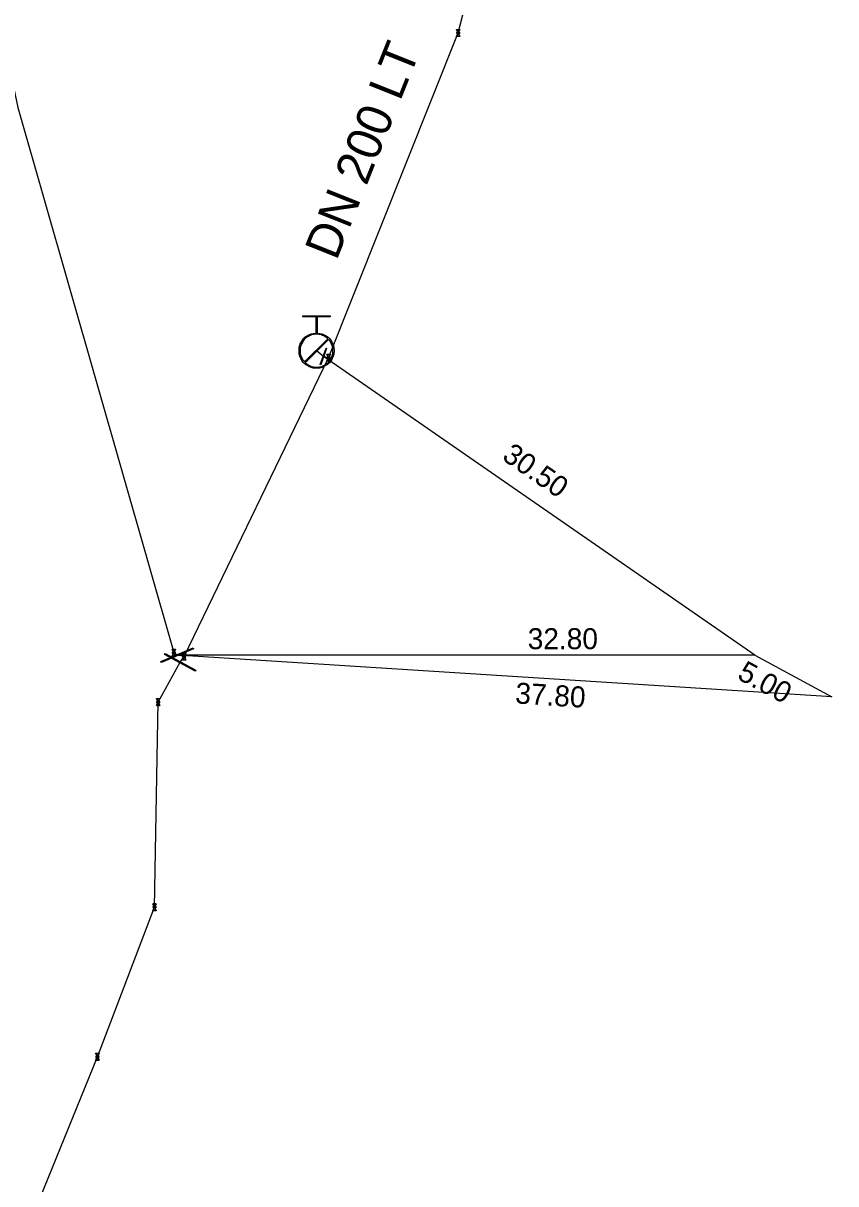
# Model space of a CAD drawing. Extents: x -820257 to -819974, y -1070894 to -1070484.
# Drawn here: x -820183 to -820136.6, y -1070688.1 to -1070621.8 of the extents above; entities that cross this region are included whole.
import ezdxf

# ---------------------------------------------------------------- set-up
doc = ezdxf.new("R2010")
doc.units = 0
for name, color, linetype in [('Hyd-odbočka', 7, 'Continuous'), ('Hyd-šoupě', 7, 'Continuous'), ('Hydrant', 7, 'Continuous'), ('Lomový bod vodovodu', 7, 'Continuous'), ('Oměrka vodovodu', 7, 'Continuous'), ('Oměrka-text', 7, 'Continuous'), ('Roz-řad', 7, 'Continuous'), ('Roz-řad-popis základní', 7, 'Continuous'), ('Řad-šoupě', 7, 'Continuous')]:
    doc.layers.add(name, color=color, linetype=linetype)

msp = doc.modelspace()

# ---------------------------------------------------------------- linework, layer by layer
at = {"layer": 'Hyd-odbočka'}
for p, q in [((-820165.86, -1070640.82), (-820166.25, -1070640.49)), ((-820165.56, -1070640.89), (-820165.86, -1070640.82))]:
    msp.add_line(p, q, dxfattribs=at)
at = {"layer": 'Hyd-šoupě'}
msp.add_lwpolyline([(-820166.041, -1070641.286), (-820165.708, -1070640.343), (-820165.679, -1070640.354), (-820166.012, -1070641.297), (-820166.041, -1070641.286)], dxfattribs=at)
at = {"layer": 'Hydrant'}
for points in [[(-820166.281, -1070639.49), (-820166.281, -1070638.553), (-820167.031, -1070638.553), (-820167.031, -1070638.49), (-820165.469, -1070638.49), (-820165.469, -1070638.553), (-820166.219, -1070638.553), (-820166.219, -1070639.49)], [(-820166.936, -1070641.133), (-820165.607, -1070639.804)], [(-820165.564, -1070639.847), (-820166.893, -1070641.178)]]:
    msp.add_lwpolyline(points, dxfattribs=at)
for points in [[(-820166.219, -1070639.49), (-820165.982, -1070639.498), (-820165.758, -1070639.619), (-820165.52, -1070639.748), (-820165.385, -1070639.988), (-820165.25, -1070640.228), (-820165.25, -1070640.49), (-820165.25, -1070640.75), (-820165.382, -1070640.988), (-820165.514, -1070641.226), (-820165.752, -1070641.358), (-820165.99, -1070641.49), (-820166.25, -1070641.49), (-820166.51, -1070641.49), (-820166.748, -1070641.358), (-820166.986, -1070641.226), (-820167.118, -1070640.988), (-820167.25, -1070640.75), (-820167.25, -1070640.49), (-820167.25, -1070640.228), (-820167.115, -1070639.988), (-820166.98, -1070639.748), (-820166.742, -1070639.619), (-820166.52, -1070639.498), (-820166.281, -1070639.49)], [(-820165.607, -1070639.804), (-820165.689, -1070639.728), (-820165.789, -1070639.674), (-820166.014, -1070639.553), (-820166.25, -1070639.553), (-820166.486, -1070639.553), (-820166.711, -1070639.674), (-820166.936, -1070639.795), (-820167.062, -1070640.019), (-820167.188, -1070640.244), (-820167.188, -1070640.49), (-820167.188, -1070640.734), (-820167.063, -1070640.957), (-820167.01, -1070641.054), (-820166.936, -1070641.133)], [(-820166.893, -1070641.178), (-820166.814, -1070641.25), (-820166.717, -1070641.303), (-820166.494, -1070641.428), (-820166.25, -1070641.428), (-820166.006, -1070641.428), (-820165.782, -1070641.303), (-820165.559, -1070641.179), (-820165.436, -1070640.957), (-820165.313, -1070640.734), (-820165.313, -1070640.49), (-820165.313, -1070640.244), (-820165.439, -1070640.019), (-820165.494, -1070639.924), (-820165.564, -1070639.847)]]:
    msp.add_open_spline(points, degree=3, dxfattribs=at)
at = {"layer": 'Lomový bod vodovodu'}
for points in [[(-820158.188, -1070622.266), (-820158.25, -1070622.13), (-820158.05, -1070622.13), (-820158.113, -1070622.266)], [(-820158.113, -1070622.394), (-820158.05, -1070622.53), (-820158.25, -1070622.53), (-820158.188, -1070622.394)], [(-820158.128, -1070622.259), (-820158.074, -1070622.143), (-820158.228, -1070622.143), (-820158.173, -1070622.259)], [(-820158.173, -1070622.401), (-820158.228, -1070622.518), (-820158.074, -1070622.518), (-820158.128, -1070622.401)], [(-820158.182, -1070622.383), (-820158.158, -1070622.33), (-820158.182, -1070622.277)], [(-820158.168, -1070622.27), (-820158.15, -1070622.308), (-820158.133, -1070622.27)], [(-820158.133, -1070622.39), (-820158.15, -1070622.352), (-820158.168, -1070622.39)], [(-820158.118, -1070622.277), (-820158.142, -1070622.33), (-820158.118, -1070622.383)], [(-820165.598, -1070640.826), (-820165.66, -1070640.69), (-820165.46, -1070640.69), (-820165.523, -1070640.826)], [(-820165.523, -1070640.954), (-820165.46, -1070641.09), (-820165.66, -1070641.09), (-820165.598, -1070640.954)], [(-820165.538, -1070640.819), (-820165.484, -1070640.703), (-820165.638, -1070640.703), (-820165.583, -1070640.819)], [(-820165.583, -1070640.961), (-820165.638, -1070641.078), (-820165.484, -1070641.078), (-820165.538, -1070640.961)], [(-820165.592, -1070640.943), (-820165.568, -1070640.89), (-820165.592, -1070640.837)], [(-820165.578, -1070640.83), (-820165.56, -1070640.868), (-820165.543, -1070640.83)], [(-820165.543, -1070640.95), (-820165.56, -1070640.912), (-820165.578, -1070640.95)], [(-820165.528, -1070640.837), (-820165.552, -1070640.89), (-820165.528, -1070640.943)], [(-820174.448, -1070657.686), (-820174.51, -1070657.55), (-820174.31, -1070657.55), (-820174.373, -1070657.686)], [(-820174.388, -1070657.679), (-820174.334, -1070657.563), (-820174.488, -1070657.563), (-820174.433, -1070657.679)], [(-820174.373, -1070657.814), (-820174.31, -1070657.95), (-820174.51, -1070657.95), (-820174.448, -1070657.814)], [(-820174.433, -1070657.821), (-820174.488, -1070657.938), (-820174.334, -1070657.938), (-820174.388, -1070657.821)], [(-820174.442, -1070657.803), (-820174.418, -1070657.75), (-820174.442, -1070657.697)], [(-820174.428, -1070657.69), (-820174.41, -1070657.728), (-820174.393, -1070657.69)], [(-820174.393, -1070657.81), (-820174.41, -1070657.772), (-820174.428, -1070657.81)], [(-820174.378, -1070657.697), (-820174.402, -1070657.75), (-820174.378, -1070657.803)], [(-820173.858, -1070657.906), (-820173.92, -1070657.77), (-820173.72, -1070657.77), (-820173.783, -1070657.906)], [(-820173.783, -1070658.034), (-820173.72, -1070658.17), (-820173.92, -1070658.17), (-820173.858, -1070658.034)], [(-820173.798, -1070657.899), (-820173.744, -1070657.783), (-820173.898, -1070657.783), (-820173.843, -1070657.899)], [(-820173.843, -1070658.041), (-820173.898, -1070658.158), (-820173.744, -1070658.158), (-820173.798, -1070658.041)], [(-820173.852, -1070658.023), (-820173.828, -1070657.97), (-820173.852, -1070657.917)], [(-820173.838, -1070657.91), (-820173.82, -1070657.948), (-820173.803, -1070657.91)], [(-820173.803, -1070658.03), (-820173.82, -1070657.992), (-820173.838, -1070658.03)], [(-820173.788, -1070657.917), (-820173.812, -1070657.97), (-820173.788, -1070658.023)], [(-820175.338, -1070660.516), (-820175.4, -1070660.38), (-820175.2, -1070660.38), (-820175.263, -1070660.516)], [(-820175.263, -1070660.644), (-820175.2, -1070660.78), (-820175.4, -1070660.78), (-820175.338, -1070660.644)], [(-820175.278, -1070660.509), (-820175.224, -1070660.393), (-820175.378, -1070660.393), (-820175.323, -1070660.509)], [(-820175.323, -1070660.651), (-820175.378, -1070660.768), (-820175.224, -1070660.768), (-820175.278, -1070660.651)], [(-820175.332, -1070660.633), (-820175.308, -1070660.58), (-820175.332, -1070660.527)], [(-820175.318, -1070660.52), (-820175.3, -1070660.558), (-820175.283, -1070660.52)], [(-820175.283, -1070660.64), (-820175.3, -1070660.602), (-820175.318, -1070660.64)], [(-820175.268, -1070660.527), (-820175.292, -1070660.58), (-820175.268, -1070660.633)], [(-820175.548, -1070672.236), (-820175.61, -1070672.1), (-820175.41, -1070672.1), (-820175.473, -1070672.236)], [(-820175.488, -1070672.229), (-820175.434, -1070672.113), (-820175.588, -1070672.113), (-820175.533, -1070672.229)], [(-820175.542, -1070672.353), (-820175.518, -1070672.3), (-820175.542, -1070672.247)], [(-820175.528, -1070672.24), (-820175.51, -1070672.278), (-820175.493, -1070672.24)], [(-820175.478, -1070672.247), (-820175.502, -1070672.3), (-820175.478, -1070672.353)], [(-820175.473, -1070672.364), (-820175.41, -1070672.5), (-820175.61, -1070672.5), (-820175.548, -1070672.364)], [(-820175.533, -1070672.371), (-820175.588, -1070672.488), (-820175.434, -1070672.488), (-820175.488, -1070672.371)], [(-820175.493, -1070672.36), (-820175.51, -1070672.322), (-820175.528, -1070672.36)], [(-820178.818, -1070680.786), (-820178.88, -1070680.65), (-820178.68, -1070680.65), (-820178.743, -1070680.786)], [(-820178.758, -1070680.779), (-820178.704, -1070680.663), (-820178.858, -1070680.663), (-820178.803, -1070680.779)], [(-820178.812, -1070680.903), (-820178.788, -1070680.85), (-820178.812, -1070680.797)], [(-820178.798, -1070680.79), (-820178.78, -1070680.828), (-820178.763, -1070680.79)], [(-820178.763, -1070680.91), (-820178.78, -1070680.872), (-820178.798, -1070680.91)], [(-820178.748, -1070680.797), (-820178.772, -1070680.85), (-820178.748, -1070680.903)], [(-820178.743, -1070680.914), (-820178.68, -1070681.05), (-820178.88, -1070681.05), (-820178.818, -1070680.914)], [(-820178.803, -1070680.921), (-820178.858, -1070681.038), (-820178.704, -1070681.038), (-820178.758, -1070680.921)]]:
    msp.add_lwpolyline(points, dxfattribs=at)
for points in [[(-820158.188, -1070622.394), (-820158.205, -1070622.385), (-820158.215, -1070622.367), (-820158.225, -1070622.35), (-820158.225, -1070622.33), (-820158.225, -1070622.31), (-820158.215, -1070622.293), (-820158.205, -1070622.275), (-820158.188, -1070622.266)], [(-820158.182, -1070622.277), (-820158.196, -1070622.285), (-820158.204, -1070622.299), (-820158.212, -1070622.314), (-820158.212, -1070622.33), (-820158.212, -1070622.346), (-820158.204, -1070622.361), (-820158.196, -1070622.375), (-820158.182, -1070622.383)], [(-820158.173, -1070622.259), (-820158.162, -1070622.255), (-820158.15, -1070622.255), (-820158.139, -1070622.255), (-820158.128, -1070622.259)], [(-820158.128, -1070622.401), (-820158.138, -1070622.405), (-820158.15, -1070622.405), (-820158.162, -1070622.405), (-820158.173, -1070622.401)], [(-820158.133, -1070622.27), (-820158.141, -1070622.268), (-820158.15, -1070622.268), (-820158.159, -1070622.268), (-820158.168, -1070622.27)], [(-820158.168, -1070622.39), (-820158.159, -1070622.392), (-820158.15, -1070622.392), (-820158.141, -1070622.392), (-820158.133, -1070622.39)], [(-820158.118, -1070622.383), (-820158.104, -1070622.375), (-820158.096, -1070622.361), (-820158.088, -1070622.346), (-820158.088, -1070622.33), (-820158.088, -1070622.314), (-820158.096, -1070622.299), (-820158.104, -1070622.285), (-820158.118, -1070622.277)], [(-820158.113, -1070622.266), (-820158.095, -1070622.275), (-820158.085, -1070622.293), (-820158.075, -1070622.31), (-820158.075, -1070622.33), (-820158.075, -1070622.35), (-820158.085, -1070622.367), (-820158.095, -1070622.385), (-820158.113, -1070622.394)], [(-820165.598, -1070640.954), (-820165.615, -1070640.945), (-820165.625, -1070640.927), (-820165.635, -1070640.91), (-820165.635, -1070640.89), (-820165.635, -1070640.87), (-820165.625, -1070640.853), (-820165.615, -1070640.835), (-820165.598, -1070640.826)], [(-820165.592, -1070640.837), (-820165.606, -1070640.845), (-820165.614, -1070640.859), (-820165.622, -1070640.874), (-820165.622, -1070640.89), (-820165.622, -1070640.906), (-820165.614, -1070640.921), (-820165.606, -1070640.935), (-820165.592, -1070640.943)], [(-820165.583, -1070640.819), (-820165.572, -1070640.815), (-820165.56, -1070640.815), (-820165.549, -1070640.815), (-820165.538, -1070640.819)], [(-820165.538, -1070640.961), (-820165.548, -1070640.965), (-820165.56, -1070640.965), (-820165.572, -1070640.965), (-820165.583, -1070640.961)], [(-820165.543, -1070640.83), (-820165.551, -1070640.828), (-820165.56, -1070640.828), (-820165.569, -1070640.828), (-820165.578, -1070640.83)], [(-820165.578, -1070640.95), (-820165.569, -1070640.952), (-820165.56, -1070640.952), (-820165.551, -1070640.952), (-820165.543, -1070640.95)], [(-820165.528, -1070640.943), (-820165.514, -1070640.935), (-820165.506, -1070640.921), (-820165.498, -1070640.906), (-820165.498, -1070640.89), (-820165.498, -1070640.874), (-820165.506, -1070640.859), (-820165.514, -1070640.845), (-820165.528, -1070640.837)], [(-820165.523, -1070640.826), (-820165.505, -1070640.835), (-820165.495, -1070640.853), (-820165.485, -1070640.87), (-820165.485, -1070640.89), (-820165.485, -1070640.91), (-820165.495, -1070640.927), (-820165.505, -1070640.945), (-820165.523, -1070640.954)], [(-820174.448, -1070657.814), (-820174.465, -1070657.805), (-820174.475, -1070657.787), (-820174.485, -1070657.77), (-820174.485, -1070657.75), (-820174.485, -1070657.73), (-820174.475, -1070657.713), (-820174.465, -1070657.695), (-820174.448, -1070657.686)], [(-820174.442, -1070657.697), (-820174.456, -1070657.705), (-820174.464, -1070657.719), (-820174.472, -1070657.734), (-820174.472, -1070657.75), (-820174.472, -1070657.766), (-820174.464, -1070657.781), (-820174.456, -1070657.795), (-820174.442, -1070657.803)], [(-820174.433, -1070657.679), (-820174.422, -1070657.675), (-820174.41, -1070657.675), (-820174.399, -1070657.675), (-820174.388, -1070657.679)], [(-820174.388, -1070657.821), (-820174.398, -1070657.825), (-820174.41, -1070657.825), (-820174.422, -1070657.825), (-820174.433, -1070657.821)], [(-820174.393, -1070657.69), (-820174.401, -1070657.688), (-820174.41, -1070657.688), (-820174.419, -1070657.688), (-820174.428, -1070657.69)], [(-820174.428, -1070657.81), (-820174.419, -1070657.812), (-820174.41, -1070657.812), (-820174.401, -1070657.812), (-820174.393, -1070657.81)], [(-820174.378, -1070657.803), (-820174.364, -1070657.795), (-820174.356, -1070657.781), (-820174.348, -1070657.766), (-820174.348, -1070657.75), (-820174.348, -1070657.734), (-820174.356, -1070657.719), (-820174.364, -1070657.705), (-820174.378, -1070657.697)], [(-820174.373, -1070657.686), (-820174.355, -1070657.695), (-820174.345, -1070657.713), (-820174.335, -1070657.73), (-820174.335, -1070657.75), (-820174.335, -1070657.77), (-820174.345, -1070657.787), (-820174.355, -1070657.805), (-820174.373, -1070657.814)], [(-820173.858, -1070658.034), (-820173.875, -1070658.025), (-820173.885, -1070658.007), (-820173.895, -1070657.99), (-820173.895, -1070657.97), (-820173.895, -1070657.95), (-820173.885, -1070657.933), (-820173.875, -1070657.915), (-820173.858, -1070657.906)], [(-820173.852, -1070657.917), (-820173.866, -1070657.925), (-820173.874, -1070657.939), (-820173.882, -1070657.954), (-820173.882, -1070657.97), (-820173.882, -1070657.986), (-820173.874, -1070658.001), (-820173.866, -1070658.015), (-820173.852, -1070658.023)], [(-820173.843, -1070657.899), (-820173.832, -1070657.895), (-820173.82, -1070657.895), (-820173.809, -1070657.895), (-820173.798, -1070657.899)], [(-820173.798, -1070658.041), (-820173.808, -1070658.045), (-820173.82, -1070658.045), (-820173.832, -1070658.045), (-820173.843, -1070658.041)], [(-820173.803, -1070657.91), (-820173.811, -1070657.908), (-820173.82, -1070657.908), (-820173.829, -1070657.908), (-820173.838, -1070657.91)], [(-820173.838, -1070658.03), (-820173.829, -1070658.032), (-820173.82, -1070658.032), (-820173.811, -1070658.032), (-820173.803, -1070658.03)], [(-820173.788, -1070658.023), (-820173.774, -1070658.015), (-820173.766, -1070658.001), (-820173.758, -1070657.986), (-820173.758, -1070657.97), (-820173.758, -1070657.954), (-820173.766, -1070657.939), (-820173.774, -1070657.925), (-820173.788, -1070657.917)], [(-820173.783, -1070657.906), (-820173.765, -1070657.915), (-820173.755, -1070657.933), (-820173.745, -1070657.95), (-820173.745, -1070657.97), (-820173.745, -1070657.99), (-820173.755, -1070658.007), (-820173.765, -1070658.025), (-820173.783, -1070658.034)], [(-820175.338, -1070660.644), (-820175.355, -1070660.635), (-820175.365, -1070660.617), (-820175.375, -1070660.6), (-820175.375, -1070660.58), (-820175.375, -1070660.56), (-820175.365, -1070660.543), (-820175.355, -1070660.525), (-820175.338, -1070660.516)], [(-820175.332, -1070660.527), (-820175.346, -1070660.535), (-820175.354, -1070660.549), (-820175.362, -1070660.564), (-820175.362, -1070660.58), (-820175.362, -1070660.596), (-820175.354, -1070660.611), (-820175.346, -1070660.625), (-820175.332, -1070660.633)], [(-820175.323, -1070660.509), (-820175.312, -1070660.505), (-820175.3, -1070660.505), (-820175.289, -1070660.505), (-820175.278, -1070660.509)], [(-820175.278, -1070660.651), (-820175.288, -1070660.655), (-820175.3, -1070660.655), (-820175.312, -1070660.655), (-820175.323, -1070660.651)], [(-820175.283, -1070660.52), (-820175.291, -1070660.518), (-820175.3, -1070660.518), (-820175.309, -1070660.518), (-820175.318, -1070660.52)], [(-820175.318, -1070660.64), (-820175.309, -1070660.642), (-820175.3, -1070660.642), (-820175.291, -1070660.642), (-820175.283, -1070660.64)], [(-820175.268, -1070660.633), (-820175.254, -1070660.625), (-820175.246, -1070660.611), (-820175.238, -1070660.596), (-820175.238, -1070660.58), (-820175.238, -1070660.564), (-820175.246, -1070660.549), (-820175.254, -1070660.535), (-820175.268, -1070660.527)], [(-820175.263, -1070660.516), (-820175.245, -1070660.525), (-820175.235, -1070660.543), (-820175.225, -1070660.56), (-820175.225, -1070660.58), (-820175.225, -1070660.6), (-820175.235, -1070660.617), (-820175.245, -1070660.635), (-820175.263, -1070660.644)], [(-820175.548, -1070672.364), (-820175.565, -1070672.355), (-820175.575, -1070672.337), (-820175.585, -1070672.32), (-820175.585, -1070672.3), (-820175.585, -1070672.28), (-820175.575, -1070672.263), (-820175.565, -1070672.245), (-820175.548, -1070672.236)], [(-820175.542, -1070672.247), (-820175.556, -1070672.255), (-820175.564, -1070672.269), (-820175.572, -1070672.284), (-820175.572, -1070672.3), (-820175.572, -1070672.316), (-820175.564, -1070672.331), (-820175.556, -1070672.345), (-820175.542, -1070672.353)], [(-820175.533, -1070672.229), (-820175.522, -1070672.225), (-820175.51, -1070672.225), (-820175.499, -1070672.225), (-820175.488, -1070672.229)], [(-820175.493, -1070672.24), (-820175.501, -1070672.238), (-820175.51, -1070672.238), (-820175.519, -1070672.238), (-820175.528, -1070672.24)], [(-820175.478, -1070672.353), (-820175.464, -1070672.345), (-820175.456, -1070672.331), (-820175.448, -1070672.316), (-820175.448, -1070672.3), (-820175.448, -1070672.284), (-820175.456, -1070672.269), (-820175.464, -1070672.255), (-820175.478, -1070672.247)], [(-820175.473, -1070672.236), (-820175.455, -1070672.245), (-820175.445, -1070672.263), (-820175.435, -1070672.28), (-820175.435, -1070672.3), (-820175.435, -1070672.32), (-820175.445, -1070672.337), (-820175.455, -1070672.355), (-820175.473, -1070672.364)], [(-820175.488, -1070672.371), (-820175.498, -1070672.375), (-820175.51, -1070672.375), (-820175.522, -1070672.375), (-820175.533, -1070672.371)], [(-820175.528, -1070672.36), (-820175.519, -1070672.362), (-820175.51, -1070672.362), (-820175.501, -1070672.362), (-820175.493, -1070672.36)], [(-820178.818, -1070680.914), (-820178.835, -1070680.905), (-820178.845, -1070680.887), (-820178.855, -1070680.87), (-820178.855, -1070680.85), (-820178.855, -1070680.83), (-820178.845, -1070680.813), (-820178.835, -1070680.795), (-820178.818, -1070680.786)], [(-820178.812, -1070680.797), (-820178.826, -1070680.805), (-820178.834, -1070680.819), (-820178.842, -1070680.834), (-820178.842, -1070680.85), (-820178.842, -1070680.866), (-820178.834, -1070680.881), (-820178.826, -1070680.895), (-820178.812, -1070680.903)], [(-820178.803, -1070680.779), (-820178.792, -1070680.775), (-820178.78, -1070680.775), (-820178.769, -1070680.775), (-820178.758, -1070680.779)], [(-820178.763, -1070680.79), (-820178.771, -1070680.788), (-820178.78, -1070680.788), (-820178.789, -1070680.788), (-820178.798, -1070680.79)], [(-820178.748, -1070680.903), (-820178.734, -1070680.895), (-820178.726, -1070680.881), (-820178.718, -1070680.866), (-820178.718, -1070680.85), (-820178.718, -1070680.834), (-820178.726, -1070680.819), (-820178.734, -1070680.805), (-820178.748, -1070680.797)], [(-820178.743, -1070680.786), (-820178.725, -1070680.795), (-820178.715, -1070680.813), (-820178.705, -1070680.83), (-820178.705, -1070680.85), (-820178.705, -1070680.87), (-820178.715, -1070680.887), (-820178.725, -1070680.905), (-820178.743, -1070680.914)], [(-820178.758, -1070680.921), (-820178.768, -1070680.925), (-820178.78, -1070680.925), (-820178.792, -1070680.925), (-820178.803, -1070680.921)], [(-820178.798, -1070680.91), (-820178.789, -1070680.912), (-820178.78, -1070680.912), (-820178.771, -1070680.912), (-820178.763, -1070680.91)]]:
    msp.add_open_spline(points, degree=3, dxfattribs=at)
at = {"layer": 'Oměrka vodovodu'}
for p, q in [((-820141.186, -1070657.893), (-820165.86, -1070640.82)), ((-820136.785, -1070660.266), (-820174.21, -1070657.89)), ((-820141.186, -1070657.893), (-820174.21, -1070657.89)), ((-820141.186, -1070657.893), (-820136.785, -1070660.266))]:
    msp.add_line(p, q, dxfattribs=at)
at = {"layer": 'Roz-řad'}
for p, q in [((-820174.21, -1070657.89), (-820174.41, -1070657.75)), ((-820173.82, -1070657.97), (-820174.21, -1070657.89)), ((-820174.05, -1070658.3), (-820173.82, -1070657.97))]:
    msp.add_line(p, q, dxfattribs=at)
for points in [[(-820173.82, -1070657.97), (-820165.56, -1070640.89), (-820158.15, -1070622.33), (-820156.54, -1070616.06), (-820145.77, -1070596.81), (-820140.37, -1070592.75), (-820129.37, -1070571.15), (-820123.84, -1070560.28), (-820117.608, -1070563.82), (-820117.26, -1070563.21)], [(-820192.294, -1070583.934), (-820183.322, -1070626.593), (-820174.41, -1070657.75)], [(-820203.65, -1070730.98), (-820194.91, -1070715.48), (-820193.87, -1070716.11), (-820182.33, -1070693.6), (-820183.71, -1070692.98), (-820178.78, -1070680.85), (-820175.51, -1070672.3), (-820175.3, -1070660.58), (-820174.05, -1070658.3)]]:
    msp.add_lwpolyline(points, dxfattribs=at)
at = {"layer": 'Řad-šoupě'}
for points in [[(-820175.144, -1070658.247), (-820173.299, -1070657.476), (-820173.275, -1070657.534), (-820175.12, -1070658.305), (-820175.144, -1070658.247)], [(-820173.188, -1070658.808), (-820174.942, -1070657.848), (-820174.912, -1070657.793), (-820173.158, -1070658.753), (-820173.188, -1070658.808)]]:
    msp.add_lwpolyline(points, dxfattribs=at)

# ---------------------------------------------------------------- texts
at = {"layer": 'Oměrka-text'}
for s, rotation, p in [('30.50', 325.3189, (-820155.705, -1070646.678)), ('32.80', 359.99563, (-820154.178, -1070657.553)), (' 5.00', 331.66539, (-820142.655, -1070659.006)), ('37.80', 356.36789, (-820154.916, -1070660.649))]:
    msp.add_text(s, height=1.2, rotation=rotation, dxfattribs=at).set_placement(p)
at = {"layer": 'Roz-řad-popis základní'}
msp.add_text('DN 200 LT', height=2, rotation=68.23584, dxfattribs=at).set_placement((-820165.112, -1070635.391))

doc.saveas('drawing.dxf')
